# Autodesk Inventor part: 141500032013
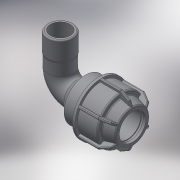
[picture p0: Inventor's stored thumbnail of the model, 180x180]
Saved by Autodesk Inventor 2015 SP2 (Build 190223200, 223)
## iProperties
Created: 2017-08
Part Number: 141500032013
Material: Generic
Description: L.14 90° ELBOW FEMALE ADAPTOR (SILVER) 32-1.1/4"
Document SubType Name: Modeling
Designer: KIM
Density: 1 g/cm^3
Appearance: Default
Author: KIM
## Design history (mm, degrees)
derived "141500.ipt"
feature "Solid1::141500.ipt"
feature "Solid2::141500.ipt"
tag "TaggingFeature1"
body "Solid1"
body "Solid2"
other parameters: "d1" = 32, "d2" = 56, "d4" = 15 deg, "d5" = 36.96, "d6" = 12.1968, "d10" = 61, "d16" = 32.64, "d17" = 2.8, "d22" = 51.2, "d24" = 2.8, "d25" = 54.9, "d26" = 45.75, "d27" = 2.8, "d28" = 135 deg, "d29" = 1.68, "d31" = 1.6, "d46" = 150 deg, "d49" = 3.05, "d50" = 0, "d58" = 0.96, "d61" = 360 deg, "d63" = 28.8, "d94" = 66, "d95" = 38.952, "d96" = 50.6376, "d97" = 25, "d98" = 31.1616, "d99" = 45.57384, "d100" = 135 deg, "d108" = 1.6, "d112" = 32.5, "d113" = 75, "d114" = 57.12, "d115" = 45.57384, "d116" = 45 deg, "d117" = 0, "d118" = 0, "d_" = 32, "G_" = 38.952, "E_" = 61, "A_" = 75, "l_" = 56, "l_2" = 25, "A_1" = 66
